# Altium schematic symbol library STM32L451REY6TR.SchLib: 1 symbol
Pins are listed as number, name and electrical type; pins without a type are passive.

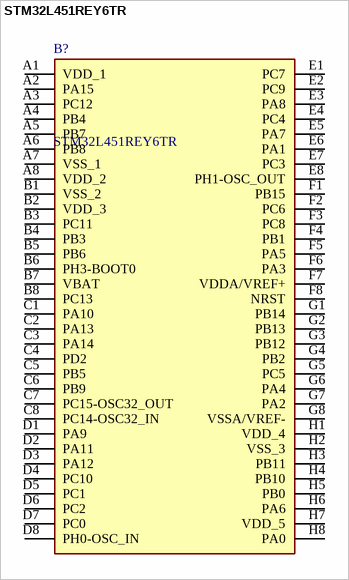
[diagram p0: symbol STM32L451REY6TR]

## STM32L451REY6TR
designator B?
ARM Microcontrollers - MCU 16/32-BITS MICROS; Manufacturer_Name: STMicroelectronics; Geometry.Height: 0.585mm
footprint BGA64C40P8X8_336X366X58
pins: A1 VDD_1, A2 PA15, A3 PC12, A4 PB4, A5 PB7, A6 PB8, A7 VSS_1, A8 VDD_2, B1 VSS_2, B2 VDD_3, B3 PC11, B4 PB3, B5 PB6, B6 PH3-BOOT0, B7 VBAT, B8 PC13, C1 PA10, C2 PA13, C3 PA14, C4 PD2, C5 PB5, C6 PB9, C7 PC15-OSC32_OUT, C8 PC14-OSC32_IN, D1 PA9, D2 PA11, D3 PA12, D4 PC10, D5 PC1, D6 PC2, D7 PC0, D8 PH0-OSC_IN, E1 PC7, E2 PC9, E3 PA8, E4 PC4, E5 PA7, E6 PA1, E7 PC3, E8 PH1-OSC_OUT, F1 PB15, F2 PC6, F3 PC8, F4 PB1, F5 PA5, F6 PA3, F7 VDDA/VREF+, F8 NRST, G1 PB14, G2 PB13, G3 PB12, G4 PB2, G5 PC5, G6 PA4, G7 PA2, G8 VSSA/VREF-, H1 VDD_4, H2 VSS_3, H3 PB11, H4 PB10, H5 PB0, H6 PA6, H7 VDD_5, H8 PA0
